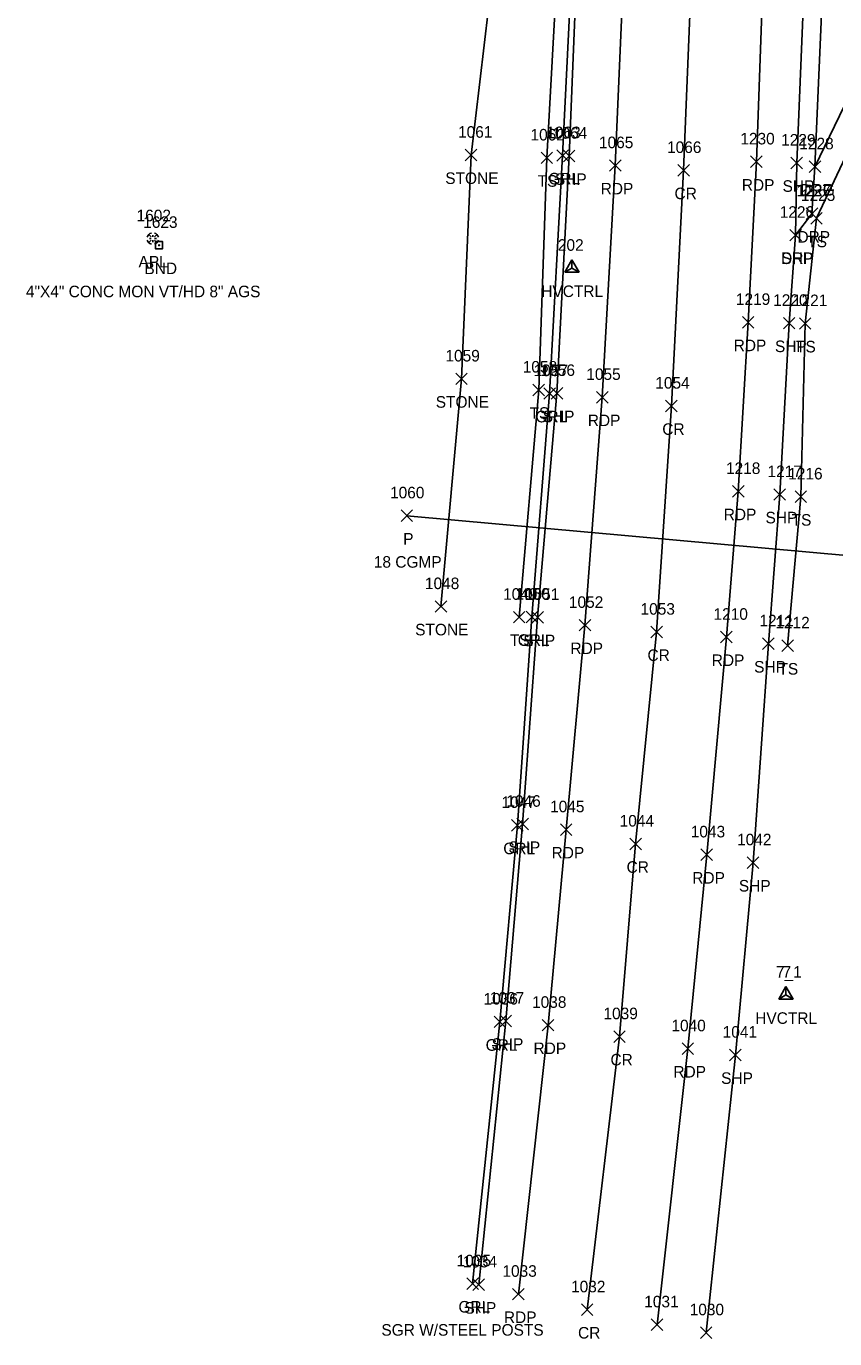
# Model space of a CAD drawing. Extents: x 1618262 to 1622220, y 273782 to 283685.
# Drawn here: x 1621946.2 to 1622086.2, y 282355.4 to 282582.4 of the extents above; entities that cross this region are included whole.
import ezdxf

# ---------------------------------------------------------------- set-up
doc = ezdxf.new("R2010")
doc.units = 0
for name, color, linetype in [('C_A', 7, 'Continuous'), ('C_I', 7, 'Continuous'), ('CPSM', 7, 'Continuous'), ('D_A', 7, 'Continuous'), ('D_C', 7, 'Continuous'), ('D_I', 7, 'Continuous'), ('D_TIC', 7, 'Continuous'), ('DCP', 7, 'Continuous'), ('L_A', 7, 'Continuous'), ('L_I', 7, 'Continuous'), ('L_TIC', 7, 'Continuous'), ('LASF', 7, 'Continuous'), ('LELB', 7, 'Continuous'), ('M_A', 7, 'Continuous'), ('M_C', 7, 'Continuous'), ('M_I', 7, 'Continuous'), ('MHBP', 7, 'Continuous'), ('MMP', 7, 'Continuous'), ('P_A', 7, 'Continuous'), ('P_I', 7, 'Continuous'), ('P_TIC', 7, 'Continuous'), ('PET', 7, 'Continuous'), ('PRC', 7, 'Continuous'), ('PSP', 7, 'Continuous'), ('R_A', 7, 'Continuous'), ('R_C', 7, 'Continuous'), ('R_I', 7, 'Continuous'), ('R_TIC', 7, 'Continuous'), ('RDG', 7, 'Continuous'), ('RDP', 7, 'Continuous'), ('RGR', 7, 'Continuous')]:
    doc.layers.add(name, color=color, linetype=linetype)

msp = doc.modelspace()

# ---------------------------------------------------------------- linework, layer by layer
at = {"layer": 'CPSM'}
for p, q in [((1622039.42, 282539.87), (1622040.67, 282542.03)), ((1622041.92, 282539.87), (1622040.67, 282542.03)), ((1622040.67, 282540.59), (1622040.67, 282542.03)), ((1622039.42, 282539.87), (1622040.67, 282540.59)), ((1622039.42, 282539.87), (1622041.92, 282539.87)), ((1622040.67, 282540.59), (1622040.67, 282540.59)), ((1622040.67, 282540.59), (1622041.92, 282539.87)), ((1622076.45, 282414.12), (1622077.7, 282416.29)), ((1622076.45, 282414.12), (1622077.7, 282416.29)), ((1622076.45, 282414.12), (1622077.7, 282414.84)), ((1622076.45, 282414.12), (1622077.7, 282414.84)), ((1622078.95, 282414.12), (1622077.7, 282416.29)), ((1622077.7, 282414.84), (1622077.7, 282416.29)), ((1622078.95, 282414.12), (1622077.7, 282416.29)), ((1622077.7, 282414.84), (1622077.7, 282416.29)), ((1622077.7, 282414.84), (1622077.7, 282414.84)), ((1622077.7, 282414.84), (1622078.95, 282414.12)), ((1622077.7, 282414.84), (1622077.7, 282414.84)), ((1622077.7, 282414.84), (1622078.95, 282414.12)), ((1622076.45, 282414.12), (1622078.95, 282414.12)), ((1622076.45, 282414.12), (1622078.95, 282414.12))]:
    msp.add_line(p, q, dxfattribs=at)
at = {"layer": 'D_TIC'}
for points in [[(1622011.08, 282496.76), (1622013.08, 282498.76)], [(1622013.08, 282496.76), (1622011.08, 282498.76)]]:
    msp.add_lwpolyline(points, dxfattribs=at)
at = {"layer": 'DCP'}
msp.add_lwpolyline([(1622012.08, 282497.76), (1622104.81, 282489.39)], dxfattribs=at)
at = {"layer": 'L_TIC'}
for points in [[(1622022.2, 282559.15), (1622024.2, 282561.15)], [(1622024.2, 282559.15), (1622022.2, 282561.15)], [(1622035.31, 282558.67), (1622037.31, 282560.67)], [(1622037.31, 282558.67), (1622035.31, 282560.67)], [(1622081.99, 282548.21), (1622083.99, 282550.21)], [(1622083.99, 282548.21), (1622081.99, 282550.21)], [(1622080.04, 282530.01), (1622082.04, 282532.01)], [(1622082.04, 282530.01), (1622080.04, 282532.01)], [(1622020.54, 282520.44), (1622022.54, 282522.44)], [(1622022.54, 282520.44), (1622020.54, 282522.44)], [(1622033.92, 282518.52), (1622035.92, 282520.52)], [(1622035.92, 282518.52), (1622033.92, 282520.52)], [(1622079.28, 282500.03), (1622081.28, 282502.03)], [(1622081.28, 282500.03), (1622079.28, 282502.03)], [(1622016.99, 282481.05), (1622018.99, 282483.05)], [(1622018.99, 282481.05), (1622016.99, 282483.05)], [(1622030.53, 282479.21), (1622032.53, 282481.21)], [(1622032.53, 282479.21), (1622030.53, 282481.21)], [(1622077, 282474.26), (1622079, 282476.26)], [(1622079, 282474.26), (1622077, 282476.26)]]:
    msp.add_lwpolyline(points, dxfattribs=at)
at = {"layer": 'LASF'}
msp.add_lwpolyline([(1622017.99, 282482.05), (1622021.54, 282521.44), (1622023.2, 282560.15), (1622027.72, 282598.27), (1622026.16, 282633.94), (1622026.88, 282675.28), (1622029.94, 282679.45), (1622032.97, 282688.79), (1622033.09, 282693.39), (1622031.46, 282708.81), (1622023.77, 282712.35), (1622021.82, 282710.84), (1622017.17, 282709.22), (1622015.05, 282702.04), (1622004.92, 282698.84), (1621996.66, 282681.56), (1622000.41, 282659.07)], dxfattribs=at)
at = {"layer": 'LELB'}
for points in [[(1622031.53, 282480.21), (1622034.92, 282519.52), (1622036.31, 282559.67), (1622038.55, 282600.48), (1622040.58, 282634.79), (1622041.38, 282671.63), (1622041.06, 282708.26), (1622040.54, 282746.86), (1622039.33, 282766.47), (1622038.37, 282807.15), (1622037, 282847.69), (1622035.47, 282881.36), (1622030.12, 282906.9), (1622032.2, 282930.97)], [(1622078, 282475.26), (1622080.28, 282501.03), (1622081.04, 282531.01), (1622082.99, 282549.21), (1622091.59, 282567.42), (1622098.83, 282572.85), (1622113.97, 282572.38)]]:
    msp.add_lwpolyline(points, dxfattribs=at)
at = {"layer": 'MHBP'}
msp.add_lwpolyline([(1621968.56, 282545.18), (1621969.81, 282545.18), (1621969.81, 282543.93), (1621968.56, 282543.93)], close=True, dxfattribs=at)
msp.add_circle((1621969.19, 282544.55), 0.0833, dxfattribs=at)
at = {"layer": 'MMP'}
for p, q in [((1621967.49, 282546.34), (1621967.85, 282545.98)), ((1621968.13, 282546), (1621968.13, 282546.3)), ((1621968.41, 282545.98), (1621968.77, 282546.34)), ((1621967.49, 282545.06), (1621967.85, 282545.42)), ((1621967.53, 282545.7), (1621967.83, 282545.7)), ((1621968.13, 282545.1), (1621968.13, 282545.4)), ((1621968.41, 282545.42), (1621968.77, 282545.06)), ((1621968.43, 282545.7), (1621968.73, 282545.7))]:
    msp.add_line(p, q, dxfattribs=at)
for start, end in [(105, 165), (15, 75), (195, 255), (285, 345)]:
    msp.add_arc((1621968.13, 282545.7), 1, start, end, dxfattribs=at)
at = {"layer": 'P_TIC'}
for points in [[(1622039.19, 282558.98), (1622041.19, 282560.98)], [(1622041.19, 282558.98), (1622039.19, 282560.98)], [(1622071.59, 282557.99), (1622073.59, 282559.99)], [(1622073.59, 282557.99), (1622071.59, 282559.99)], [(1622078.58, 282557.79), (1622080.58, 282559.79)], [(1622080.58, 282557.79), (1622078.58, 282559.79)], [(1622047.16, 282557.34), (1622049.16, 282559.34)], [(1622049.16, 282557.34), (1622047.16, 282559.34)], [(1622058.99, 282556.51), (1622060.99, 282558.51)], [(1622060.99, 282556.51), (1622058.99, 282558.51)], [(1622078.38, 282545.3), (1622080.38, 282547.3)], [(1622080.38, 282545.3), (1622078.38, 282547.3)], [(1622070.17, 282530.22), (1622072.17, 282532.22)], [(1622072.17, 282530.22), (1622070.17, 282532.22)], [(1622077.27, 282530.06), (1622079.27, 282532.06)], [(1622079.27, 282530.06), (1622077.27, 282532.06)], [(1622037.06, 282517.94), (1622039.06, 282519.94)], [(1622039.06, 282517.94), (1622037.06, 282519.94)], [(1622044.92, 282517.25), (1622046.92, 282519.25)], [(1622046.92, 282517.25), (1622044.92, 282519.25)], [(1622056.87, 282515.74), (1622058.87, 282517.74)], [(1622058.87, 282515.74), (1622056.87, 282517.74)], [(1622068.45, 282500.97), (1622070.45, 282502.97)], [(1622070.45, 282500.97), (1622068.45, 282502.97)], [(1622075.63, 282500.43), (1622077.63, 282502.43)], [(1622077.63, 282500.43), (1622075.63, 282502.43)], [(1622033.72, 282479.17), (1622035.72, 282481.17)], [(1622035.72, 282479.17), (1622033.72, 282481.17)], [(1622041.91, 282477.81), (1622043.91, 282479.81)], [(1622043.91, 282477.81), (1622041.91, 282479.81)], [(1622054.31, 282476.63), (1622056.31, 282478.63)], [(1622056.31, 282476.63), (1622054.31, 282478.63)], [(1622066.39, 282475.75), (1622068.39, 282477.75)], [(1622068.39, 282475.75), (1622066.39, 282477.75)], [(1622073.67, 282474.61), (1622075.67, 282476.61)], [(1622075.67, 282474.61), (1622073.67, 282476.61)], [(1622031.13, 282443.4), (1622033.13, 282445.4)], [(1622033.13, 282443.4), (1622031.13, 282445.4)], [(1622038.66, 282442.45), (1622040.66, 282444.45)], [(1622040.66, 282442.45), (1622038.66, 282444.45)], [(1622050.69, 282439.97), (1622052.69, 282441.97)], [(1622052.69, 282439.97), (1622050.69, 282441.97)], [(1622063, 282438.1), (1622065, 282440.1)], [(1622065, 282438.1), (1622063, 282440.1)], [(1622071.02, 282436.73), (1622073.02, 282438.73)], [(1622073.02, 282436.73), (1622071.02, 282438.73)], [(1622028.22, 282409.34), (1622030.22, 282411.34)], [(1622030.22, 282409.34), (1622028.22, 282411.34)], [(1622035.53, 282408.61), (1622037.53, 282410.61)], [(1622037.53, 282408.61), (1622035.53, 282410.61)], [(1622047.9, 282406.64), (1622049.9, 282408.64)], [(1622049.9, 282406.64), (1622047.9, 282408.64)], [(1622059.73, 282404.55), (1622061.73, 282406.55)], [(1622061.73, 282404.55), (1622059.73, 282406.55)], [(1622067.96, 282403.45), (1622069.96, 282405.45)], [(1622069.96, 282403.45), (1622067.96, 282405.45)], [(1622023.53, 282363.7), (1622025.53, 282365.7)], [(1622025.53, 282363.7), (1622023.53, 282365.7)], [(1622030.4, 282362.08), (1622032.4, 282364.08)], [(1622032.4, 282362.08), (1622030.4, 282364.08)], [(1622042.29, 282359.39), (1622044.29, 282361.39)], [(1622044.29, 282359.39), (1622042.29, 282361.39)], [(1622054.39, 282356.79), (1622056.39, 282358.79)], [(1622056.39, 282356.79), (1622054.39, 282358.79)], [(1622062.9, 282355.42), (1622064.9, 282357.42)], [(1622064.9, 282355.42), (1622062.9, 282357.42)]]:
    msp.add_lwpolyline(points, dxfattribs=at)
at = {"layer": 'PET'}
for points in [[(1622055.39, 282357.79), (1622060.73, 282405.55), (1622064, 282439.1), (1622067.39, 282476.75), (1622069.45, 282501.97), (1622071.17, 282531.22), (1622072.59, 282558.99), (1622074.38, 282609.31), (1622075.4, 282650.49), (1622076.38, 282682.88), (1622076.73, 282709.49), (1622076.47, 282742.79), (1622075.65, 282781.75), (1622073.85, 282831.38), (1622072.41, 282861.12), (1622070.97, 282880.71), (1622069.11, 282909.86), (1622067.07, 282934.34)], [(1622031.4, 282363.08), (1622036.53, 282409.61), (1622039.66, 282443.45), (1622042.91, 282478.81), (1622045.92, 282518.25), (1622048.16, 282558.34), (1622049.91, 282599.51), (1622051.11, 282634.14), (1622051.9, 282670.59), (1622052.33, 282709.81), (1622052.15, 282746.85), (1622051.43, 282768.15), (1622050.47, 282807.31), (1622048.59, 282847.85), (1622046.49, 282883.04), (1622043.22, 282932.28)]]:
    msp.add_lwpolyline(points, dxfattribs=at)
at = {"layer": 'PRC'}
msp.add_lwpolyline([(1622043.29, 282360.39), (1622048.9, 282407.64), (1622051.69, 282440.97), (1622055.31, 282477.63), (1622057.87, 282516.74), (1622059.99, 282557.51), (1622061.58, 282597.2), (1622062.84, 282633.2), (1622063.88, 282668.54), (1622064.41, 282708.38), (1622064.5, 282747.03), (1622063.87, 282768.18), (1622062.59, 282807.54), (1622060.96, 282848.03), (1622058.91, 282883.68), (1622055.26, 282933.11)], dxfattribs=at)
at = {"layer": 'PSP'}
for points in [[(1622063.9, 282356.42), (1622068.96, 282404.45), (1622072.02, 282437.73), (1622074.67, 282475.61), (1622076.63, 282501.43), (1622078.27, 282531.06), (1622079.38, 282546.3), (1622079.58, 282558.79), (1622081.73, 282610.73), (1622082.59, 282649.97), (1622083.39, 282682.72), (1622083.74, 282709.96), (1622083.62, 282744.12), (1622083.45, 282781.35), (1622083.17, 282811.55), (1622082.7, 282831.31), (1622081.46, 282858.35), (1622080.36, 282881.43), (1622078.26, 282910.95), (1622077.13, 282929.74), (1622076.71, 282935.51)], [(1622024.53, 282364.7), (1622029.22, 282410.34), (1622032.13, 282444.4), (1622034.72, 282480.17), (1622038.06, 282518.94), (1622040.19, 282559.98), (1622041.78, 282599.8), (1622043.58, 282635.08), (1622043.93, 282671.71), (1622044.18, 282709.62), (1622044.43, 282746.88), (1622044.14, 282766.85), (1622043.31, 282807.36), (1622042.11, 282847.85), (1622040.01, 282882.11), (1622036.28, 282931.35)]]:
    msp.add_lwpolyline(points, dxfattribs=at)
at = {"layer": 'R_TIC'}
for points in [[(1622038.04, 282559.07), (1622040.04, 282561.07)], [(1622040.04, 282559.07), (1622038.04, 282561.07)], [(1622081.72, 282557.14), (1622083.72, 282559.14)], [(1622083.72, 282557.14), (1622081.72, 282559.14)], [(1622081.72, 282557.14), (1622083.72, 282559.14)], [(1622083.72, 282557.14), (1622081.72, 282559.14)], [(1622081.21, 282549), (1622083.21, 282551)], [(1622083.21, 282549), (1622081.21, 282551)], [(1622078.38, 282545.3), (1622080.38, 282547.3)], [(1622080.38, 282545.3), (1622078.38, 282547.3)], [(1622035.8, 282517.9), (1622037.8, 282519.9)], [(1622037.8, 282517.9), (1622035.8, 282519.9)], [(1622032.74, 282479.24), (1622034.74, 282481.24)], [(1622034.74, 282479.24), (1622032.74, 282481.24)], [(1622030.23, 282443.19), (1622032.23, 282445.19)], [(1622032.23, 282443.19), (1622030.23, 282445.19)], [(1622027.19, 282409.18), (1622029.19, 282411.18)], [(1622029.19, 282409.18), (1622027.19, 282411.18)], [(1622022.48, 282363.89), (1622024.48, 282365.89)], [(1622024.48, 282363.89), (1622022.48, 282365.89)]]:
    msp.add_lwpolyline(points, dxfattribs=at)
at = {"layer": 'RDG'}
msp.add_lwpolyline([(1622082.72, 282558.14), (1622088.66, 282570.41), (1622094.75, 282574.34), (1622099.08, 282575.61), (1622113.44, 282575.48), (1622128.2, 282575.3)], dxfattribs=at)
at = {"layer": 'RDP'}
msp.add_lwpolyline([(1622079.38, 282546.3), (1622082.21, 282550), (1622082.72, 282558.14), (1622084.65, 282603.02)], dxfattribs=at)
at = {"layer": 'RGR'}
msp.add_lwpolyline([(1622023.48, 282364.89), (1622028.19, 282410.18), (1622031.23, 282444.19), (1622033.74, 282480.24), (1622036.8, 282518.9), (1622039.04, 282560.07), (1622040.98, 282599.77), (1622042.92, 282635.17), (1622043.06, 282671.76), (1622043.62, 282709.36), (1622043.68, 282746.97), (1622043.35, 282766.73), (1622042.76, 282807.19), (1622041.25, 282847.72), (1622039.44, 282882.18), (1622035.13, 282907.98)], dxfattribs=at)

# ---------------------------------------------------------------- texts
at = {"layer": 'C_A'}
for p in [(1622035.36, 282535.59), (1622072.39, 282409.84), (1622072.39, 282409.84)]:
    msp.add_text('HVCTRL', height=2, dxfattribs=at).set_placement(p)
at = {"layer": 'C_I'}
for s, p in [('202', (1622038.23, 282543.59)), ('7_1', (1622075.99, 282417.84)), ('7', (1622077.13, 282417.84))]:
    msp.add_text(s, height=2, dxfattribs=at).set_placement(p)
at = {"layer": 'D_A'}
msp.add_text('P', height=2, dxfattribs=at).set_placement((1622011.46, 282492.76))
at = {"layer": 'D_C'}
msp.add_text('18 CGMP', height=2, dxfattribs=at).set_placement((1622006.37, 282488.76))
at = {"layer": 'D_I'}
msp.add_text('1060', height=2, dxfattribs=at).set_placement((1622009.18, 282500.76))
at = {"layer": 'L_A'}
for s, p in [('STONE', (1622018.74, 282555.15)), ('TS', (1622034.72, 282554.67)), ('TS', (1622081.4, 282544.21)), ('TS', (1622079.45, 282526.01)), ('STONE', (1622017.09, 282516.44)), ('TS', (1622033.33, 282514.52)), ('TS', (1622078.69, 282496.03)), ('STONE', (1622013.53, 282477.05)), ('TS', (1622029.94, 282475.21)), ('TS', (1622076.41, 282470.26))]:
    msp.add_text(s, height=2, dxfattribs=at).set_placement(p)
at = {"layer": 'L_I'}
for s, p in [('1061', (1622020.95, 282563.15)), ('1062', (1622033.49, 282562.67)), ('1225', (1622080.3, 282552.21)), ('1221', (1622078.91, 282534.01)), ('1059', (1622018.77, 282524.44)), ('1058', (1622032.15, 282522.52)), ('1216', (1622078.1, 282504.03)), ('1048', (1622015.22, 282485.05)), ('1049', (1622028.75, 282483.21)), ('1212', (1622075.87, 282478.26))]:
    msp.add_text(s, height=2, dxfattribs=at).set_placement(p)
at = {"layer": 'M_A'}
for s, p in [('APL', (1621965.64, 282540.7)), ('BND', (1621966.67, 282539.55))]:
    msp.add_text(s, height=2, dxfattribs=at).set_placement(p)
at = {"layer": 'M_C'}
msp.add_text('4"X4" CONC MON VT/HD 8" AGS', height=2, dxfattribs=at).set_placement((1621946.15, 282535.55))
at = {"layer": 'M_I'}
for s, p in [('1602', (1621965.31, 282548.7)), ('1623', (1621966.45, 282547.55))]:
    msp.add_text(s, height=2, dxfattribs=at).set_placement(p)
at = {"layer": 'P_A'}
for s, p in [('SHP', (1622037.72, 282554.98)), ('RDP', (1622045.64, 282553.34)), ('RDP', (1622070.07, 282553.99)), ('SHP', (1622077.12, 282553.79)), ('CR', (1622058.42, 282552.51)), ('SHP', (1622076.92, 282541.3)), ('RDP', (1622068.66, 282526.22)), ('SHP', (1622075.81, 282526.06)), ('SHP', (1622035.6, 282513.94)), ('RDP', (1622043.41, 282513.25)), ('CR', (1622056.3, 282511.74)), ('RDP', (1622066.94, 282496.97)), ('SHP', (1622074.17, 282496.43)), ('SHP', (1622032.26, 282475.17)), ('RDP', (1622040.4, 282473.81)), ('CR', (1622053.74, 282472.63)), ('RDP', (1622064.87, 282471.75)), ('SHP', (1622072.2, 282470.61)), ('SHP', (1622029.67, 282439.4)), ('RDP', (1622037.14, 282438.45)), ('CR', (1622050.12, 282435.97)), ('RDP', (1622061.49, 282434.1)), ('SHP', (1622069.56, 282432.73)), ('SHP', (1622026.76, 282405.34)), ('RDP', (1622034.02, 282404.61)), ('CR', (1622047.33, 282402.64)), ('RDP', (1622058.22, 282400.55)), ('SHP', (1622066.49, 282399.45)), ('SHP', (1622022.07, 282359.7)), ('RDP', (1622028.89, 282358.08)), ('CR', (1622041.72, 282355.39))]:
    msp.add_text(s, height=2, dxfattribs=at).set_placement(p)
at = {"layer": 'P_I'}
for s, p in [('1064', (1622037.37, 282562.98)), ('1065', (1622045.34, 282561.34)), ('1066', (1622057.12, 282560.51)), ('1230', (1622069.81, 282561.99)), ('1229', (1622076.88, 282561.79)), ('1226', (1622076.63, 282549.3)), ('1219', (1622069.04, 282534.22)), ('1220', (1622075.49, 282534.06)), ('1056', (1622035.24, 282521.94)), ('1055', (1622043.15, 282521.25)), ('1054', (1622055.09, 282519.74)), ('1218', (1622067.33, 282504.97)), ('1217', (1622074.51, 282504.43)), ('1051', (1622032.52, 282483.17)), ('1052', (1622040.14, 282481.81)), ('1053', (1622052.54, 282480.63)), ('1210', (1622065.17, 282479.75)), ('1211', (1622073.11, 282478.61)), ('1046', (1622029.31, 282447.4)), ('1045', (1622036.88, 282446.45)), ('1044', (1622048.92, 282443.97)), ('1043', (1622061.23, 282442.1)), ('1042', (1622069.25, 282440.73)), ('1037', (1622026.45, 282413.34)), ('1038', (1622033.76, 282412.61)), ('1039', (1622046.12, 282410.64)), ('1040', (1622057.88, 282408.55)), ('1041', (1622066.75, 282407.45)), ('1034', (1622021.76, 282367.7)), ('1033', (1622028.63, 282366.08)), ('1032', (1622040.51, 282363.39)), ('1031', (1622053.18, 282360.79)), ('1030', (1622061.04, 282359.42))]:
    msp.add_text(s, height=2, dxfattribs=at).set_placement(p)
at = {"layer": 'R_A'}
for s, p in [('GRL', (1622036.58, 282555.07)), ('DRG', (1622080.2, 282553.14)), ('DRP', (1622080.2, 282553.14)), ('DRP', (1622079.7, 282545)), ('DRP', (1622076.87, 282541.3)), ('GRL', (1622034.35, 282513.9)), ('GRL', (1622031.28, 282475.24)), ('GRL', (1622028.78, 282439.19)), ('GRL', (1622025.73, 282405.18)), ('GRL', (1622021.02, 282359.89))]:
    msp.add_text(s, height=2, dxfattribs=at).set_placement(p)
at = {"layer": 'R_C'}
msp.add_text('SGR W/STEEL POSTS', height=2, dxfattribs=at).set_placement((1622007.68, 282355.89))
at = {"layer": 'R_I'}
for s, p in [('1063', (1622036.22, 282563.07)), ('1228', (1622080.02, 282561.14)), ('1228', (1622080.02, 282561.14)), ('1227', (1622079.52, 282553)), ('1226', (1622076.63, 282549.3)), ('1057', (1622034.03, 282521.9)), ('1050', (1622030.88, 282483.24)), ('1047', (1622028.46, 282447.19)), ('1036', (1622025.36, 282413.18)), ('1035', (1622020.7, 282367.89))]:
    msp.add_text(s, height=2, dxfattribs=at).set_placement(p)

doc.saveas('drawing.dxf')
